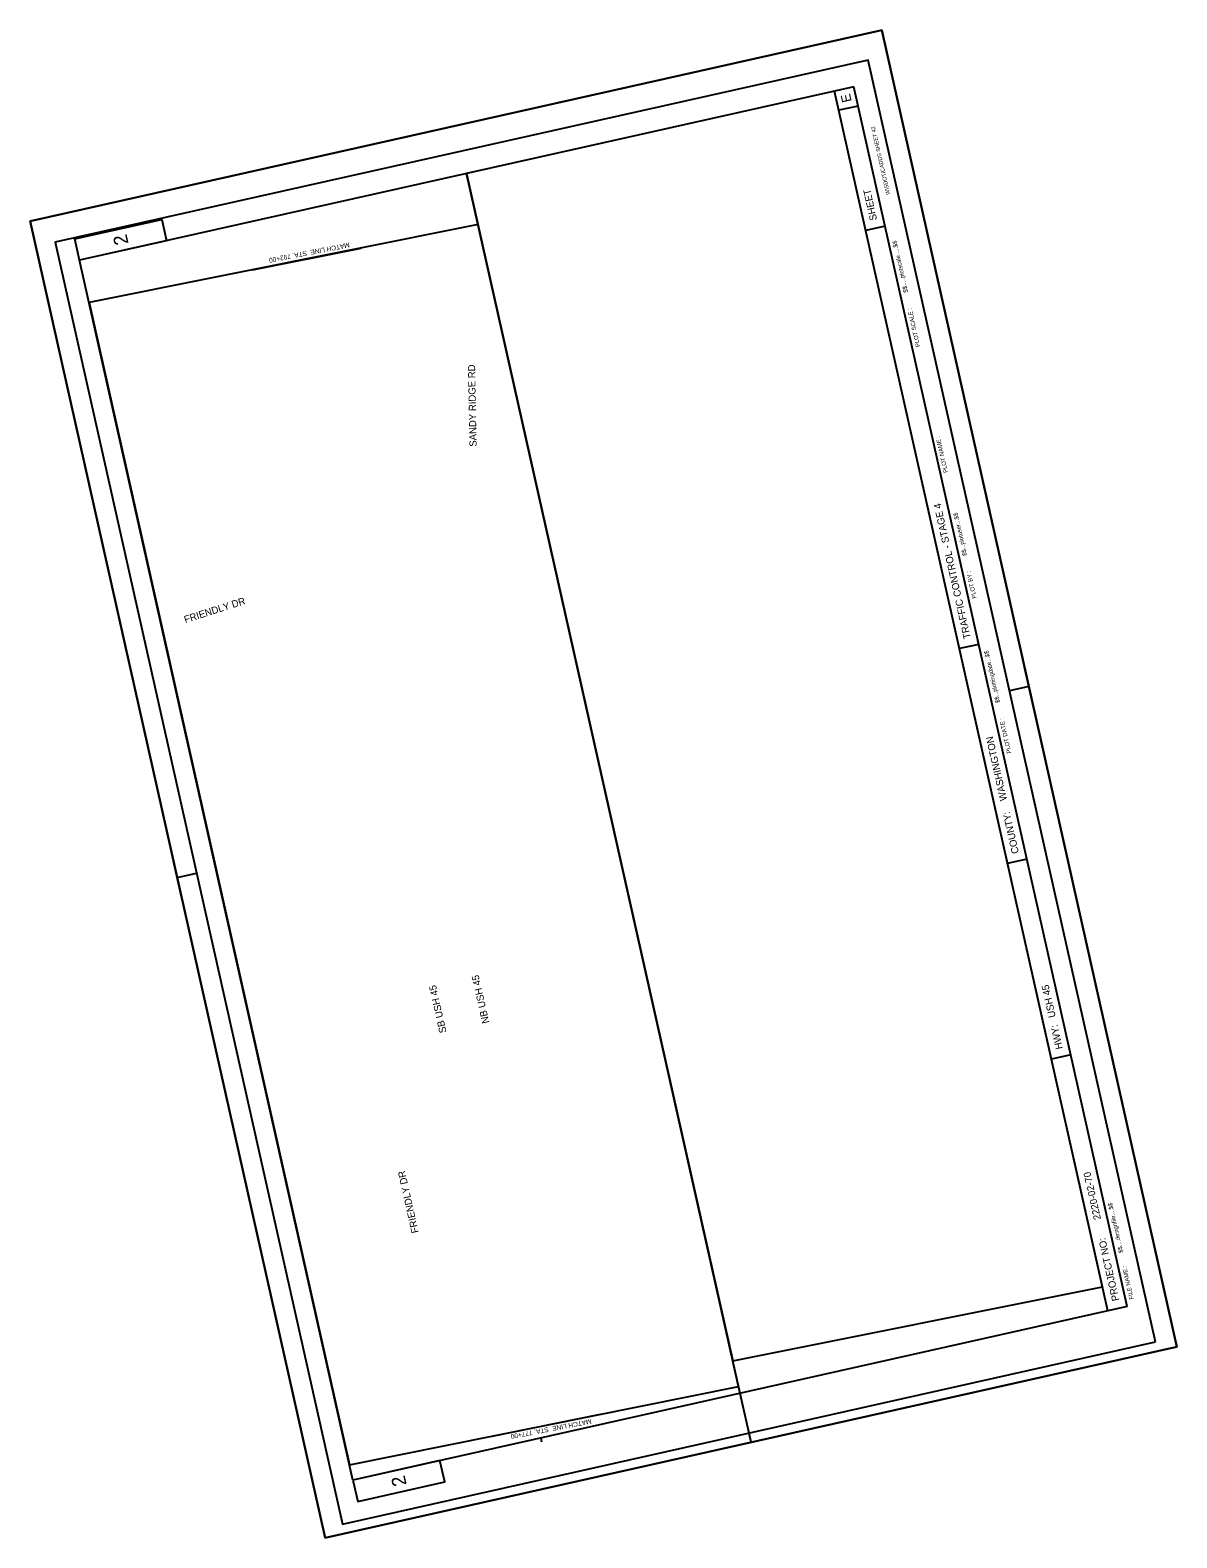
# Model space of a CAD drawing. Extents: x 355507 to 356952, y 199440 to 201339.
import ezdxf

# ---------------------------------------------------------------- set-up
doc = ezdxf.new("R2010")
doc.units = 0
for name, color, linetype in [('Default', 7, 'Continuous'), ('P_ALI_20', 7, 'Continuous'), ('P_ALI_200_Equation', 7, 'Continuous'), ('P_ALI_20_Tic', 7, 'Continuous'), ('P_ALI_50_Equation', 7, 'Continuous'), ('P_ALI_50_PIData', 7, 'Continuous'), ('P_ALI_50_Tic', 7, 'Continuous')]:
    doc.layers.add(name, color=color, linetype=linetype)

msp = doc.modelspace()

# ---------------------------------------------------------------- linework, layer by layer
for p, q in [((356579.9, 201339.1), (356531.1, 201328.2)), ((356590.9, 201290.3), (356579.9, 201339.1)), ((356544.6, 201267.9), (355568.9, 201049.2)), ((356889.1, 199731.1), (356544.6, 201267.9)), ((356864.8, 199725.6), (356520.2, 201262.4)), ((356550.1, 201243.5), (356525.7, 201238.1)), ((356401.3, 199621.7), (356056.7, 201158.5)), ((355555.3, 201109.4), (355506.6, 201098.5)), ((355517.5, 201049.7), (355506.6, 201098.5)), ((356584, 201092.3), (356559.6, 201086.8)), ((355913.4, 199512.3), (355568.9, 201049.2)), ((356702.1, 200565.3), (356677.7, 200559.9)), ((356770.8, 200487.7), (356759.8, 200536.5)), ((356765.3, 200512.1), (356740.9, 200506.7)), ((355697.4, 200247.1), (355686.5, 200295.9)), ((356762.8, 200294.6), (356738.4, 200289.1)), ((355691.9, 200271.5), (355716.3, 200277)), ((356818.1, 200048.2), (356793.7, 200042.7)), ((356889.1, 199731.1), (355913.4, 199512.3)), ((356951.8, 199680.3), (356940.8, 199729.1)), ((356951.8, 199680.3), (356903, 199669.3)), ((356393.1, 199658.3), (356393.1, 199658.3)), ((356415.1, 199560), (356401.3, 199621.7)), ((356150, 199565.4), (356151.1, 199560.5)), ((356439.5, 199565.4), (356390.7, 199554.5)), ((355878.4, 199439.7), (355867.5, 199488.5)), ((355927.2, 199450.6), (355878.4, 199439.7))]:
    msp.add_line(p, q)
for points in [[(355568.9, 201049.2), (355562.8, 201076), (355672.6, 201100.6), (355678.6, 201073.8)], [(355913.4, 199512.3), (355919.4, 199485.5), (356029.2, 199510.1), (356023.1, 199536.9)]]:
    msp.add_lwpolyline(points, close=True)
at = {"layer": 'Default'}
for points in [[(356392.1, 199662.6), (356857.9, 199756.1), (356520.2, 201262.4), (356056.7, 201158.5)], [(356392.1, 199662.6), (356857.9, 199756.1), (356520.2, 201262.4), (356056.7, 201158.5)], [(356392.1, 199662.6), (356857.9, 199756.1), (356520.2, 201262.4), (356056.7, 201158.5)], [(355909, 199531.8), (356399.3, 199630.2), (356071.2, 201094.2), (355580.8, 200995.9)], [(355909, 199531.8), (356399.3, 199630.2), (356071.2, 201094.2), (355580.8, 200995.9)], [(355909, 199531.8), (356399.3, 199630.2), (356071.2, 201094.2), (355580.8, 200995.9)]]:
    msp.add_lwpolyline(points, close=True, dxfattribs=at)
at = {"layer": 'P_ALI_20'}
for points in [[(356951.8, 199680.3), (356579.9, 201339.1), (355506.6, 201098.5), (355878.4, 199439.7)], [(356924.8, 199686.5), (356562.7, 201301.4), (355538.2, 201071.8), (355900.2, 199456.8)]]:
    msp.add_lwpolyline(points, close=True, dxfattribs=at)
at = {"layer": 'P_ALI_200_Equation'}
msp.add_lwpolyline([(355878.4, 199439.7), (355506.6, 201098.5), (356579.9, 201339.1), (356951.8, 199680.3), (355878.4, 199439.7)], dxfattribs=at)
at = {"layer": 'P_ALI_20_Tic'}
msp.add_lwpolyline([(355878.4, 199439.7), (355506.6, 201098.5), (356579.9, 201339.1), (356951.8, 199680.3)], close=True, dxfattribs=at)
at = {"layer": 'P_ALI_50_Equation'}
for p, q in [((355787, 201037.2), (355923.6, 201064.6)), ((356088.9, 199567.9), (356225.4, 199595.3))]:
    msp.add_line(p, q, dxfattribs=at)
at = {"layer": 'P_ALI_50_Tic'}
msp.add_lwpolyline([(356520.2, 201262.4), (356056.7, 201158.5)], dxfattribs=at)

# ---------------------------------------------------------------- texts
for s, height, rotation, p in [('E', 12, 102.6348, (356542, 201249.5)), ('WISDOT/CADDS SHEET 42', 5, 102.6348, (356590.4, 201132.3)), ('SHEET ', 9, 102.6348, (356574, 201100.3)), ('2', 17.5, 102.6348, (355630.7, 201070.4)), ('$$.....plotscale.....$$', 5.4, 102.6348, (356612.9, 201009.1)), ('PLOT SCALE : ', 5.4, 102.6348, (356628.3, 200940.6)), ('PLOT NAME :                      ', 5.4, 102.6348, (356663.3, 200782.1)), ('TRAFFIC CONTROL - STAGE 4', 9, 102.6348, (356692.1, 200573.4)), ('$$...plotuser...$$', 5.4, 102.6347, (356687.3, 200677.3)), ('PLOT BY :', 5.4, 102.6347, (356699.3, 200623.6)), ('$$...plottingdate...$$', 5.4, 102.6347, (356728.8, 200491.9)), ('PLOT DATE :', 5.4, 102.6347, (356743.1, 200428.5)), (' WASHINGTON', 9, 102.6348, (356738.6, 200366)), ('COUNTY:', 9, 102.6348, (356752.8, 200302.6)), (' USH 45', 9, 102.6348, (356799.9, 200092.8)), ('HWY:', 9, 102.6348, (356808.1, 200056.2)), (' 2220-02-70', 9, 102.6348, (356856.9, 199838.1)), ('$$....designfile....$$', 5.4, 102.6347, (356884.1, 199799.1)), ('PROJECT NO:', 9, 102.6348, (356879.2, 199739.1)), ('FILE NAME :', 5.4, 102.6348, (356897.3, 199740.6)), ('2', 17.5, 102.6348, (355981.2, 199506.7))]:
    msp.add_text(s, height=height, rotation=rotation).set_placement(p)
at = {"layer": 'P_ALI_50_PIData'}
for s, height, rotation, p in [('MATCH LINE  STA. 792+00', 6, 190.9331, (355908.6, 201071.5)), ('SANDY RIDGE RD', 9, 91.0961, (356069.3, 200814.4)), ('FRIENDLY DR', 9, 17.6385, (355702.2, 200592)), ('NB USH 45', 9, 102.6348, (356085.3, 200088.8)), ('SB USH 45', 9, 102.6348, (356031.4, 200076.7)), ('FRIENDLY DR', 9, 102.6348, (355996.3, 199824.6)), ('MATCH LINE  STA. 777+00', 6, 190.9331, (356213.3, 199589.6))]:
    msp.add_text(s, height=height, rotation=rotation, dxfattribs=at).set_placement(p)

doc.saveas('drawing.dxf')
